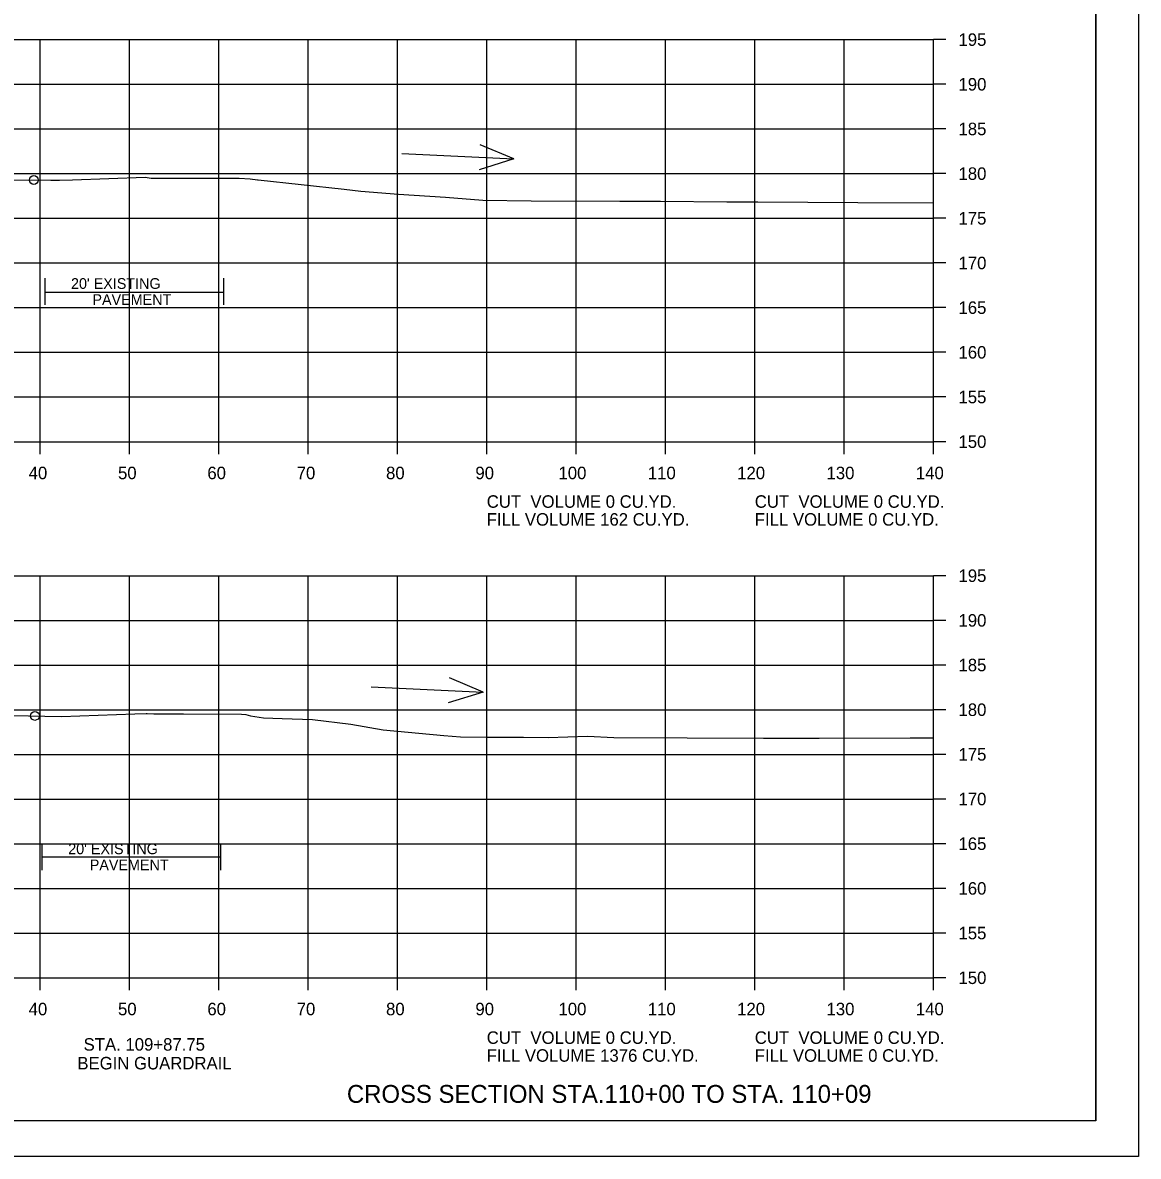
# Model space of a CAD drawing. Extents: x 915787 to 919910, y 133456 to 136717.
# Drawn here: x 916452 to 916576.9, y 134309.4 to 134436.3 of the extents above; entities that cross this region are included whole.
import ezdxf

# ---------------------------------------------------------------- set-up
doc = ezdxf.new("R2010")
doc.units = 0
for name, color, linetype in [('R_Axis', 7, 'Continuous'), ('R_Axis Annot', 7, 'Continuous'), ('R_Border', 7, 'Continuous'), ('R_Border Notes', 7, 'Continuous'), ('R_Draft', 7, 'Continuous'), ('R_Drive', 7, 'Continuous'), ('R_Exist Surface', 7, 'Continuous'), ('R_Exist Surface Annot', 7, 'Continuous'), ('R_Grid', 7, 'Continuous'), ('R_No Plot', 7, 'Continuous'), ('R_Water Annot', 7, 'Continuous')]:
    doc.layers.add(name, color=color, linetype=linetype)

msp = doc.modelspace()

# ---------------------------------------------------------------- linework, layer by layer
at = {"layer": 'R_Axis'}
for p, q in [((916553.98, 134389.37), (916553.98, 134434.37)), ((916555.38, 134434.37), (916553.98, 134434.37)), ((916555.38, 134429.37), (916553.98, 134429.37)), ((916555.38, 134424.37), (916553.98, 134424.37)), ((916555.38, 134419.37), (916553.98, 134419.37)), ((916555.38, 134414.37), (916553.98, 134414.37)), ((916555.38, 134409.37), (916553.98, 134409.37)), ((916555.38, 134404.37), (916553.98, 134404.37)), ((916555.38, 134399.37), (916553.98, 134399.37)), ((916555.38, 134394.37), (916553.98, 134394.37)), ((916273.98, 134389.37), (916553.98, 134389.37)), ((916453.98, 134387.97), (916453.98, 134389.37)), ((916463.98, 134387.97), (916463.98, 134389.37)), ((916473.98, 134387.97), (916473.98, 134389.37)), ((916483.98, 134387.97), (916483.98, 134389.37)), ((916493.98, 134387.97), (916493.98, 134389.37)), ((916503.98, 134387.97), (916503.98, 134389.37)), ((916513.98, 134387.97), (916513.98, 134389.37)), ((916523.98, 134387.97), (916523.98, 134389.37)), ((916533.98, 134387.97), (916533.98, 134389.37)), ((916543.98, 134387.97), (916543.98, 134389.37)), ((916553.98, 134387.97), (916553.98, 134389.37)), ((916555.38, 134389.37), (916553.98, 134389.37)), ((916553.98, 134329.37), (916553.98, 134374.37)), ((916555.38, 134374.37), (916553.98, 134374.37)), ((916555.38, 134369.37), (916553.98, 134369.37)), ((916555.38, 134364.37), (916553.98, 134364.37)), ((916555.38, 134359.37), (916553.98, 134359.37)), ((916555.38, 134354.37), (916553.98, 134354.37)), ((916555.38, 134349.37), (916553.98, 134349.37)), ((916555.38, 134344.37), (916553.98, 134344.37)), ((916555.38, 134339.37), (916553.98, 134339.37)), ((916555.38, 134334.37), (916553.98, 134334.37)), ((916273.98, 134329.37), (916553.98, 134329.37)), ((916453.98, 134327.97), (916453.98, 134329.37)), ((916463.98, 134327.97), (916463.98, 134329.37)), ((916473.98, 134327.97), (916473.98, 134329.37)), ((916483.98, 134327.97), (916483.98, 134329.37)), ((916493.98, 134327.97), (916493.98, 134329.37)), ((916503.98, 134327.97), (916503.98, 134329.37)), ((916513.98, 134327.97), (916513.98, 134329.37)), ((916523.98, 134327.97), (916523.98, 134329.37)), ((916533.98, 134327.97), (916533.98, 134329.37)), ((916543.98, 134327.97), (916543.98, 134329.37)), ((916553.98, 134327.97), (916553.98, 134329.37)), ((916555.38, 134329.37), (916553.98, 134329.37))]:
    msp.add_line(p, q, dxfattribs=at)
at = {"layer": 'R_Border'}
for q in [(916572.16, 134518.83), (916255.98, 134313.37)]:
    msp.add_line((916572.16, 134313.37), q, dxfattribs=at)
at = {"layer": 'R_Exist Surface'}
for points in [[(916449.5, 134418.66), (916455.2, 134418.65), (916456.18, 134418.63), (916457.62, 134418.68), (916465.76, 134418.97), (916466.43, 134418.88), (916466.59, 134418.87), (916470.2, 134418.86), (916476.26, 134418.85), (916477.52, 134418.77), (916478.31, 134418.68), (916478.36, 134418.67), (916478.4, 134418.66), (916488.04, 134417.63), (916489.87, 134417.39), (916494.11, 134417.09), (916499.38, 134416.75), (916503.54, 134416.41), (916508.94, 134416.31), (916518.89, 134416.3), (916523.43, 134416.28), (916530.86, 134416.21), (916534.31, 134416.21), (916545.5, 134416.14), (916553.98, 134416.11)], [(916450.82, 134358.72), (916456.38, 134358.62), (916464.59, 134358.92), (916465.87, 134358.96), (916465.98, 134358.95), (916466.71, 134358.91), (916470.05, 134358.9), (916476.53, 134358.88), (916477.01, 134358.82), (916477.55, 134358.69), (916479, 134358.46), (916481.09, 134358.37), (916484.47, 134358.26), (916488.77, 134357.74), (916492.4, 134357.11), (916499.18, 134356.48), (916501.03, 134356.33), (916503.91, 134356.29), (916508.08, 134356.29), (916510.87, 134356.26), (916515.26, 134356.4), (916518.19, 134356.25), (916526.41, 134356.23), (916534.96, 134356.18), (916541.2, 134356.19), (916551.38, 134356.22), (916553.98, 134356.21)]]:
    msp.add_lwpolyline(points, dxfattribs=at)
at = {"layer": 'R_Exist Surface Annot'}
for p, q in [((916454.53, 134407.67), (916454.53, 134404.67)), ((916474.53, 134407.67), (916474.53, 134404.67)), ((916454.53, 134406.09), (916474.53, 134406.09)), ((916454.19, 134344.4), (916454.19, 134341.4)), ((916474.19, 134344.4), (916474.19, 134341.4)), ((916454.19, 134342.9), (916474.19, 134342.9))]:
    msp.add_line(p, q, dxfattribs=at)
at = {"layer": 'R_Grid'}
for p, q in [((916273.98, 134434.37), (916553.98, 134434.37)), ((916453.98, 134389.37), (916453.98, 134434.37)), ((916463.98, 134389.37), (916463.98, 134434.37)), ((916473.98, 134389.37), (916473.98, 134434.37)), ((916483.98, 134389.37), (916483.98, 134434.37)), ((916493.98, 134389.37), (916493.98, 134434.37)), ((916503.98, 134389.37), (916503.98, 134434.37)), ((916513.98, 134389.37), (916513.98, 134434.37)), ((916523.98, 134389.37), (916523.98, 134434.37)), ((916533.98, 134389.37), (916533.98, 134434.37)), ((916543.98, 134389.37), (916543.98, 134434.37)), ((916553.98, 134389.37), (916553.98, 134434.37)), ((916273.98, 134429.37), (916553.98, 134429.37)), ((916273.98, 134424.37), (916553.98, 134424.37)), ((916273.98, 134419.37), (916553.98, 134419.37)), ((916273.98, 134414.37), (916553.98, 134414.37)), ((916273.98, 134409.37), (916553.98, 134409.37)), ((916273.98, 134404.37), (916553.98, 134404.37)), ((916273.98, 134399.37), (916553.98, 134399.37)), ((916273.98, 134394.37), (916553.98, 134394.37)), ((916273.98, 134389.37), (916553.98, 134389.37)), ((916273.98, 134374.37), (916553.98, 134374.37)), ((916453.98, 134329.37), (916453.98, 134374.37)), ((916463.98, 134329.37), (916463.98, 134374.37)), ((916473.98, 134329.37), (916473.98, 134374.37)), ((916483.98, 134329.37), (916483.98, 134374.37)), ((916493.98, 134329.37), (916493.98, 134374.37)), ((916503.98, 134329.37), (916503.98, 134374.37)), ((916513.98, 134329.37), (916513.98, 134374.37)), ((916523.98, 134329.37), (916523.98, 134374.37)), ((916533.98, 134329.37), (916533.98, 134374.37)), ((916543.98, 134329.37), (916543.98, 134374.37)), ((916553.98, 134329.37), (916553.98, 134374.37)), ((916273.98, 134369.37), (916553.98, 134369.37)), ((916273.98, 134364.37), (916553.98, 134364.37)), ((916273.98, 134359.37), (916553.98, 134359.37)), ((916273.98, 134354.37), (916553.98, 134354.37)), ((916273.98, 134349.37), (916553.98, 134349.37)), ((916273.98, 134344.37), (916553.98, 134344.37)), ((916273.98, 134339.37), (916553.98, 134339.37)), ((916273.98, 134334.37), (916553.98, 134334.37)), ((916273.98, 134329.37), (916553.98, 134329.37))]:
    msp.add_line(p, q, dxfattribs=at)
at = {"layer": 'R_No Plot'}
msp.add_line((916243.57, 134309.39), (916576.91, 134309.39), dxfattribs=at)
for points in [[(916243.57, 134522.72), (916576.91, 134522.72), (916576.91, 134309.38), (916243.57, 134309.38)], [(916489.9, 134518.83), (916489.9, 134508.95), (916525.63, 134508.95), (916525.63, 134506.03), (916548.83, 134506.03), (916548.83, 134482.81), (916572.16, 134482.81), (916572.16, 134313.37), (916255.98, 134313.37), (916255.98, 134518.83)]]:
    msp.add_lwpolyline(points, close=True, dxfattribs=at)
for centre in [(916453.29, 134418.65), (916453.41, 134358.68)]:
    msp.add_circle(centre, 0.5, dxfattribs=at)
at = {"layer": 'R_Water Annot'}
for p, q in [((916507.03, 134421.03), (916503.25, 134422.61)), ((916494.48, 134421.63), (916507.03, 134421.03)), ((916507.03, 134421.03), (916503.12, 134419.81)), ((916503.59, 134361.34), (916499.82, 134362.92)), ((916491.04, 134361.94), (916503.59, 134361.34)), ((916503.59, 134361.34), (916499.68, 134360.13))]:
    msp.add_line(p, q, dxfattribs=at)

# ---------------------------------------------------------------- texts
at = {"layer": 'R_Axis Annot'}
for s, p in [('195', (916556.78, 134433.67)), ('190', (916556.78, 134428.67)), ('185', (916556.78, 134423.67)), ('180', (916556.78, 134418.67)), ('175', (916556.78, 134413.67)), ('170', (916556.78, 134408.67)), ('165', (916556.78, 134403.67)), ('160', (916556.78, 134398.67)), ('155', (916556.78, 134393.67)), ('150', (916556.78, 134388.67)), ('40', (916452.71, 134385.17)), ('50', (916462.71, 134385.17)), ('60', (916472.71, 134385.17)), ('70', (916482.71, 134385.17)), ('80', (916492.71, 134385.17)), ('90', (916502.71, 134385.17)), ('100', (916512.01, 134385.17)), ('110', (916522.01, 134385.17)), ('120', (916532.01, 134385.17)), ('130', (916542.01, 134385.17)), ('140', (916552.01, 134385.17)), ('195', (916556.78, 134373.67)), ('190', (916556.78, 134368.67)), ('185', (916556.78, 134363.67)), ('180', (916556.78, 134358.67)), ('175', (916556.78, 134353.67)), ('170', (916556.78, 134348.67)), ('165', (916556.78, 134343.67)), ('160', (916556.78, 134338.67)), ('155', (916556.78, 134333.67)), ('150', (916556.78, 134328.67)), ('40', (916452.71, 134325.17)), ('50', (916462.71, 134325.17)), ('60', (916472.71, 134325.17)), ('70', (916482.71, 134325.17)), ('80', (916492.71, 134325.17)), ('90', (916502.71, 134325.17)), ('100', (916512.01, 134325.17)), ('110', (916522.01, 134325.17)), ('120', (916532.01, 134325.17)), ('130', (916542.01, 134325.17)), ('140', (916552.01, 134325.17))]:
    msp.add_text(s, height=1.4, dxfattribs=at).set_placement(p)
at = {"layer": 'R_Border Notes'}
for s, p in [('CUT  VOLUME 0 CU.YD.', (916503.98, 134381.97)), ('CUT  VOLUME 0 CU.YD.', (916533.98, 134381.97)), ('FILL VOLUME 162 CU.YD.', (916503.98, 134379.97)), ('FILL VOLUME 0 CU.YD.', (916533.98, 134379.97)), ('CUT  VOLUME 0 CU.YD.', (916503.98, 134321.97)), ('CUT  VOLUME 0 CU.YD.', (916533.98, 134321.97)), ('FILL VOLUME 1376 CU.YD.', (916503.98, 134319.97)), ('FILL VOLUME 0 CU.YD.', (916533.98, 134319.97))]:
    msp.add_text(s, height=1.4, dxfattribs=at).set_placement(p)
at = {"layer": 'R_Draft'}
msp.add_text('CROSS SECTION STA.110+00 TO STA. 110+09', height=2, dxfattribs=at).set_placement((916488.33, 134315.37))
at = {"layer": 'R_Drive'}
for s, p in [('STA. 109+87.75', (916458.86, 134321.21)), ('BEGIN GUARDRAIL', (916458.16, 134319.11))]:
    msp.add_text(s, height=1.4, dxfattribs=at).set_placement(p)
at = {"layer": 'R_Exist Surface Annot'}
for s, p in [("20' EXISTING", (916457.45, 134406.47)), ('PAVEMENT', (916459.85, 134404.67)), ("20' EXISTING", (916457.14, 134343.2)), ('PAVEMENT', (916459.55, 134341.4))]:
    msp.add_text(s, height=1.2, dxfattribs=at).set_placement(p)

doc.saveas('drawing.dxf')
